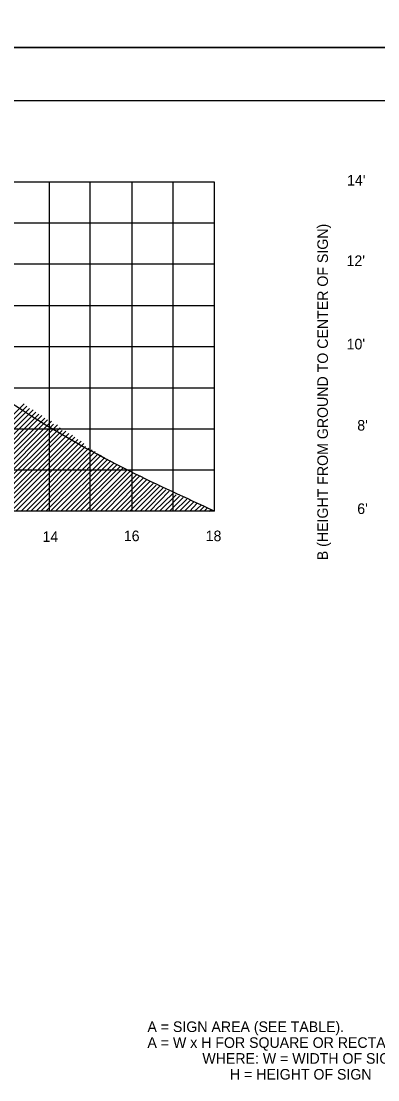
# Model space of a CAD drawing. Extents: x 644358 to 648627, y 294594 to 295782.
# Drawn here: x 645419.4 to 645520.7, y 294894.5 to 295195.1 of the extents above; entities that cross this region are included whole.
import ezdxf

# ---------------------------------------------------------------- set-up
doc = ezdxf.new("R2010")
doc.units = 0
for name, color, linetype in [('1', 7, 'Continuous'), ('10', 7, 'Continuous'), ('2', 7, 'Continuous'), ('4', 7, 'Continuous'), ('PLT-BNDY', 7, 'Continuous')]:
    doc.layers.add(name, color=color, linetype=linetype)

msp = doc.modelspace()

# ---------------------------------------------------------------- linework, layer by layer
at = {"layer": '1'}
msp.add_line((645239.31, 295172.63), (646025.31, 295172.63), dxfattribs=at)
at = {"layer": '10'}
for p, q in [((645389.8, 295056), (645420.25, 295086.45)), ((645391.18, 295056), (645421.06, 295085.76)), ((645392.55, 295056), (645421.83, 295085.15)), ((645394.05, 295056), (645422.82, 295084.77)), ((645395.43, 295056), (645423.56, 295084.14)), ((645396.93, 295056), (645424.42, 295083.5)), ((645398.3, 295056), (645425.27, 295083.1)), ((645399.68, 295056), (645426.17, 295082.36)), ((645401.18, 295056), (645426.95, 295081.91)), ((645402.55, 295056), (645428.07, 295081.52)), ((645403.93, 295056), (645428.64, 295080.72)), ((645405.3, 295056), (645429.75, 295080.45)), ((645406.68, 295056), (645430.47, 295079.67)), ((645408.05, 295056), (645431.1, 295078.92)), ((645409.55, 295056), (645432.14, 295078.72)), ((645410.93, 295056), (645432.97, 295078.05)), ((645412.3, 295056), (645433.97, 295077.55)), ((645413.68, 295056), (645434.68, 295077.01)), ((645415.05, 295056), (645435.54, 295076.37)), ((645416.55, 295056), (645436.42, 295075.87)), ((645417.93, 295056), (645437.23, 295075.18)), ((645419.43, 295056), (645437.68, 295074.38)), ((645420.8, 295056), (645438.68, 295073.88)), ((645422.18, 295056), (645439.55, 295073.38)), ((645423.68, 295056), (645440.43, 295072.88)), ((645425.05, 295056), (645441.3, 295072.25)), ((645426.43, 295056), (645442.18, 295071.88)), ((645427.8, 295056), (645443.18, 295071.25)), ((645429.18, 295056), (645444.05, 295070.75)), ((645430.68, 295056), (645444.93, 295070.25)), ((645432.05, 295056), (645445.8, 295069.75)), ((645433.43, 295056), (645446.68, 295069.25)), ((645434.8, 295056), (645447.68, 295068.75)), ((645436.18, 295056), (645448.43, 295068.25)), ((645437.68, 295056), (645449.43, 295067.63)), ((645439.05, 295056), (645450.3, 295067.25)), ((645440.43, 295056), (645451.18, 295066.75)), ((645441.93, 295056), (645452.18, 295066.25)), ((645443.3, 295056), (645453.05, 295065.88)), ((645444.8, 295056), (645454.05, 295065.38)), ((645446.18, 295056), (645455.05, 295064.88)), ((645447.55, 295056), (645455.93, 295064.38)), ((645448.93, 295056), (645456.93, 295063.88)), ((645450.3, 295056), (645457.8, 295063.38)), ((645451.68, 295056), (645458.68, 295063)), ((645453.18, 295056), (645459.68, 295062.5)), ((645454.55, 295056), (645460.55, 295062)), ((645455.93, 295056), (645461.43, 295061.63)), ((645457.3, 295056), (645462.55, 295061.13)), ((645458.68, 295056), (645463.43, 295060.63)), ((645460.18, 295056), (645464.43, 295060.25)), ((645461.55, 295056), (645465.43, 295059.88)), ((645462.93, 295056), (645466.43, 295059.38)), ((645464.43, 295056), (645467.43, 295059)), ((645465.8, 295056), (645468.43, 295058.63)), ((645467.3, 295056), (645469.3, 295058.13)), ((645468.68, 295056), (645470.43, 295057.63)), ((645470.05, 295056), (645471.3, 295057.25)), ((645471.43, 295056), (645472.3, 295056.88)), ((645472.8, 295056), (645473.3, 295056.38)), ((645474.3, 295056), (645474.3, 295056))]:
    msp.add_line(p, q, dxfattribs=at)
at = {"layer": '2'}
for p, q in [((645474.3, 295149.38), (645286.8, 295149.38)), ((645427.43, 295056), (645427.43, 295149.38)), ((645439.05, 295056), (645439.05, 295149.5)), ((645439.05, 295055.88), (645439.05, 295149.38)), ((645450.93, 295056), (645450.93, 295149.38)), ((645462.55, 295055.88), (645462.55, 295149.38)), ((645474.3, 295056), (645474.3, 295149.38)), ((645474.3, 295137.75), (645287.05, 295137.75)), ((645474.3, 295126.13), (645287.05, 295126.13)), ((645474.3, 295114.25), (645287.05, 295114.25)), ((645474.3, 295102.63), (645394.18, 295102.63)), ((645474.3, 295090.88), (645333.8, 295090.88)), ((645474.3, 295079.25), (645286.8, 295079.25)), ((645474.3, 295067.63), (645287.05, 295067.63)), ((645474.3, 295056), (645286.8, 295056))]:
    msp.add_line(p, q, dxfattribs=at)
at = {"layer": '4'}
msp.add_spline([(645474.3, 295056), (645450.43, 295067.25), (645394.55, 295103.25), (645370.93, 295128.63), (645359.43, 295149.38)], degree=3, dxfattribs=at)
at = {"layer": 'PLT-BNDY'}
for points in [[(645199.31, 295781.63), (646040.31, 295781.63), (646040.31, 295187.63), (645199.31, 295187.63)], [(645199.31, 295187.63), (646040.31, 295187.63), (646040.31, 294593.63), (645199.31, 294593.63)]]:
    msp.add_lwpolyline(points, close=True, dxfattribs=at)

# ---------------------------------------------------------------- texts
at = {"layer": '2'}
for s, p in [('14', (645425.49, 295047.24)), ('16', (645448.58, 295047.46)), ('18', (645471.83, 295047.46))]:
    msp.add_text(s, height=3, dxfattribs=at).set_placement(p)
at = {"layer": '4'}
for s, p in [("14'", (645511.98, 295148.45)), ("12'", (645511.84, 295125.6)), ("10'", (645511.86, 295101.92)), ("8'", (645514.88, 295078.87)), ("6'", (645514.87, 295055.18)), ('A = SIGN AREA (SEE TABLE).', (645455.29, 294908.07)), ('A = W x H FOR SQUARE OR RECTANGULAR SIGNS,', (645455.29, 294903.57)), ('              WHERE: W = WIDTH OF SIGN', (645455.29, 294899.07)), ('                     H = HEIGHT OF SIGN', (645455.29, 294894.57))]:
    msp.add_text(s, height=3, dxfattribs=at).set_placement(p)
msp.add_text(' B (HEIGHT FROM GROUND TO CENTER OF SIGN)', height=3.005, rotation=90, dxfattribs=at).set_placement((645506.54, 295040.93))

doc.saveas('drawing.dxf')
